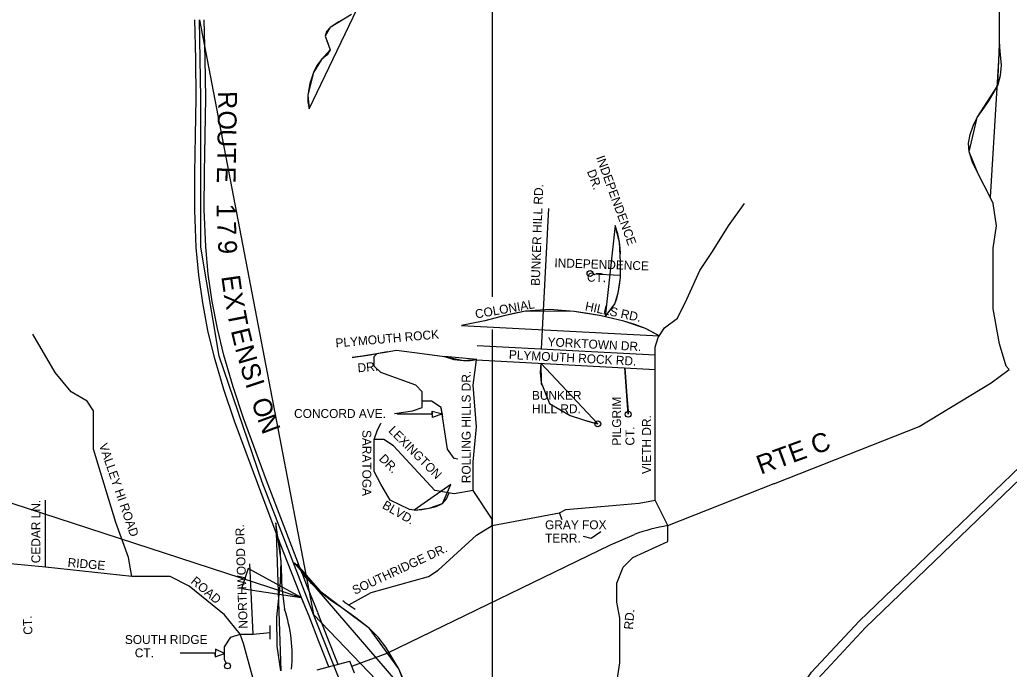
# Model space of a CAD drawing. Extents: x 5.01 to 9.58, y 0.27 to 3.39.
# Drawn here: x 6.828 to 8.037, y 1.17 to 1.964 of the extents above; entities that cross this region are included whole.
import ezdxf

# ---------------------------------------------------------------- set-up
doc = ezdxf.new("R2010")
doc.units = 0
for name, color, linetype in [('Level 7', 7, 'Continuous'), ('MO_001_NOSHOW', 7, 'Continuous'), ('MO_001_VIEW_PV', 7, 'Continuous')]:
    doc.layers.add(name, color=color, linetype=linetype)

msp = doc.modelspace()

# ---------------------------------------------------------------- linework, layer by layer
at = {"layer": 'Level 7'}
msp.add_line((5.7734, 1.7142), (7.1715, 1.2576), dxfattribs=at)
msp.add_lwpolyline([(7.1069, 1.293), (7.0988, 1.2688), (7.1715, 1.2576)], close=True, dxfattribs=at)
at = {"layer": 'MO_001_NOSHOW'}
msp.add_lwpolyline([(7.2329, 1.9703), (7.2071, 1.9544), (7.2009, 1.9437), (7.2071, 1.9269), (7.1965, 1.9153), (7.1867, 1.8993), (7.1796, 1.8718), (7.1814, 1.855), (7.4494, 2.4141)], dxfattribs=at)
for points in [[(7.1867, 1.2369), (7.124, 1.3987), (7.0714, 1.5524), (7.0491, 1.6859), (7.0491, 1.868), (7.0473, 1.9637)], [(8.0132, 1.747), (7.9988, 1.7755), (7.9876, 1.8022), (7.9976, 1.8442), (8.0227, 1.8836), (8.0249, 1.9341)], [(7.543, 1.6007), (7.5549, 1.6167), (7.5588, 1.63), (7.5616, 1.6489), (7.5619, 1.6678), (7.5604, 1.6918), (7.5553, 1.7123)], [(7.609, 1.5773), (7.5923, 1.5864), (7.5659, 1.5954), (7.5379, 1.6017), (7.5053, 1.6072), (7.4455, 1.6076), (7.4175, 1.6013), (7.3959, 1.5958), (7.3676, 1.5902)], [(7.2766, 1.558), (7.2557, 1.5538), (7.2337, 1.5508)], [(7.3468, 1.552), (7.3697, 1.5472), (7.3862, 1.5485)], [(7.4642, 1.544), (7.4646, 1.5203), (7.4748, 1.4947), (7.5004, 1.4802), (7.5179, 1.4743), (7.5339, 1.4699)], [(7.5671, 1.5385), (7.5696, 1.5042), (7.5711, 1.4816)], [(7.3095, 1.3643), (7.3281, 1.3669), (7.3442, 1.3727), (7.3546, 1.3959)], [(7.1468, 1.1678), (7.1423, 1.1983), (7.1417, 1.2336), (7.1465, 1.2762), (7.147, 1.3026), (7.1407, 1.3489)], [(7.3042, 1.1358), (7.2907, 1.1706), (7.255, 1.2198), (7.2211, 1.2449), (7.1942, 1.2653), (7.1631, 1.3001)], [(7.1977, 1.2623), (7.184, 1.2746), (7.1659, 1.2982)], [(7.4942, 0.9161), (7.4334, 0.9173), (7.3323, 0.9598), (7.2615, 1.0589), (7.2211, 1.1499), (7.1867, 1.2369)]]:
    msp.add_lwpolyline(points, close=True, dxfattribs=at)
at = {"layer": 'MO_001_VIEW_PV'}
for p, q in [((7.4051, 2.4135), (7.4051, 1.6251)), ((8.0249, 1.9341), (8.0249, 1.977)), ((7.4651, 1.5616), (7.4741, 1.733)), ((7.6935, 1.7119), (7.7131, 1.7393)), ((8.017, 1.6846), (8.021, 1.7119)), ((8.017, 1.6456), (8.017, 1.6846)), ((7.5281, 1.6534), (7.5617, 1.6517)), ((8.017, 1.6106), (8.017, 1.6456)), ((8.0249, 1.5677), (8.017, 1.6106)), ((7.4051, 1.5854), (7.4051, 0.916)), ((7.3866, 1.5657), (7.6039, 1.5541)), ((7.604, 1.5365), (7.604, 1.5637)), ((7.604, 1.3766), (7.604, 1.5365)), ((7.3316, 1.4819), (7.2889, 1.4819)), ((7.3317, 1.4837), (7.3316, 1.4819)), ((7.3818, 1.3884), (7.3818, 1.4235)), ((7.6195, 1.3455), (7.7495, 1.3969)), ((6.8594, 1.2949), (6.8594, 1.3766)), ((7.6195, 1.3455), (7.604, 1.3766)), ((7.4051, 1.3455), (7.487, 1.3611)), ((7.4904, 1.3526), (7.487, 1.3611)), ((6.8594, 1.2949), (6.8165, 1.2987)), ((6.9646, 1.2831), (6.8594, 1.2949)), ((7.1128, 1.213), (7.1089, 1.2988)), ((6.988, 1.2831), (6.9646, 1.2831)), ((7.0971, 1.213), (7.1128, 1.213)), ((7.1128, 1.213), (7.1335, 1.2149)), ((7.0664, 1.1895), (7.0236, 1.1897)), ((7.0664, 1.1873), (7.0664, 1.1895)), ((7.2334, 1.1737), (7.2765, 1.1896)), ((7.191, 1.1691), (7.231, 1.1798))]:
    msp.add_line(p, q, dxfattribs=at)
for points in [[(7.1745, 1.2513), (7.1461, 1.3238), (7.1185, 1.3966), (7.0901, 1.4732), (7.0771, 1.5118), (7.0657, 1.5509), (7.0577, 1.5841), (7.0513, 1.6177), (7.0465, 1.6515), (7.0433, 1.6855), (7.0415, 1.7311), (7.0417, 1.7767), (7.0433, 1.868), (7.0427, 1.9158), (7.0415, 1.9636)], [(7.1728, 1.2871), (7.1508, 1.3444), (7.1294, 1.4008), (7.1012, 1.4767), (7.0883, 1.5151), (7.077, 1.5539), (7.0692, 1.5866), (7.0629, 1.6196), (7.0581, 1.6529), (7.055, 1.6863), (7.0532, 1.7317), (7.0534, 1.7771), (7.055, 1.8679), (7.0544, 1.9159), (7.0532, 1.9639)], [(7.2278, 1.9669), (7.2174, 1.9613), (7.2071, 1.9544), (7.2027, 1.9494), (7.2009, 1.9437), (7.2043, 1.935), (7.2071, 1.9269), (7.2032, 1.921), (7.1965, 1.9153), (7.1906, 1.9077), (7.1867, 1.8993), (7.182, 1.8859), (7.1796, 1.8718), (7.1799, 1.8633), (7.1814, 1.855)], [(8.0132, 1.747), (8.0059, 1.7611), (7.9988, 1.7755), (7.9921, 1.7886), (7.9876, 1.8022), (7.987, 1.8128), (7.9888, 1.8236), (7.9925, 1.8341), (7.9976, 1.8442), (8.0111, 1.8639), (8.0227, 1.8836), (8.0261, 1.8957), (8.0273, 1.9084), (8.0249, 1.9341)], [(8.021, 1.7119), (8.0171, 1.7392), (8.0132, 1.747)], [(7.5617, 1.6775), (7.5612, 1.6847), (7.5604, 1.6918), (7.5583, 1.7022), (7.5553, 1.7123)], [(7.6039, 1.5638), (7.6078, 1.5755), (7.6156, 1.5872), (7.6312, 1.5989), (7.6429, 1.6223), (7.6585, 1.6573), (7.6741, 1.6807), (7.6936, 1.7119)], [(7.5543, 1.6154), (7.5546, 1.616), (7.5549, 1.6167), (7.5572, 1.6232), (7.5588, 1.63), (7.5605, 1.6394), (7.5616, 1.6489), (7.5617, 1.6503), (7.5617, 1.6517)], [(7.609, 1.5773), (7.6008, 1.5821), (7.5923, 1.5864), (7.5793, 1.5914), (7.5659, 1.5954), (7.552, 1.5988), (7.5379, 1.6017), (7.5217, 1.6047), (7.5053, 1.6072), (7.4753, 1.6095), (7.4455, 1.6076), (7.4314, 1.6048), (7.4175, 1.6013), (7.4067, 1.5985), (7.3959, 1.5958), (7.3818, 1.5928), (7.3676, 1.5902)], [(6.9646, 1.2831), (6.9607, 1.3065), (6.9451, 1.3494), (6.9179, 1.4391), (6.9179, 1.4858), (6.9101, 1.4975), (6.8906, 1.5092), (6.8711, 1.5326), (6.8438, 1.5794)], [(7.2766, 1.558), (7.2882, 1.5599), (7.3193, 1.556), (7.3466, 1.5521), (7.3468, 1.552)], [(8.0366, 1.5365), (8.0327, 1.5404), (8.0249, 1.5677)], [(7.2766, 1.558), (7.2662, 1.5558), (7.2557, 1.5538), (7.2447, 1.5522), (7.2337, 1.5508)], [(7.3193, 1.4975), (7.3193, 1.5092), (7.3116, 1.517), (7.2687, 1.5326), (7.2609, 1.5404), (7.2609, 1.5521), (7.2641, 1.5553)], [(7.3468, 1.552), (7.358, 1.5487), (7.3697, 1.5472), (7.378, 1.5474), (7.3862, 1.5485)], [(7.3817, 1.517), (7.3856, 1.5482), (7.6039, 1.5365)], [(7.4642, 1.544), (7.4635, 1.5322), (7.4646, 1.5203), (7.4649, 1.5188), (7.4652, 1.5173)], [(7.5671, 1.5385), (7.5684, 1.5214), (7.5696, 1.5042), (7.5703, 1.4947), (7.5709, 1.4852)], [(7.7511, 1.3975), (7.9264, 1.4667), (8.0147, 1.5199), (8.0366, 1.5365)], [(7.3817, 1.4235), (7.3856, 1.4663), (7.3817, 1.517)], [(7.2857, 1.4827), (7.3077, 1.4858), (7.3193, 1.4897), (7.3193, 1.4975)], [(7.3445, 1.4786), (7.3427, 1.4897), (7.331, 1.4975), (7.3193, 1.4975)], [(7.3631, 1.4266), (7.3583, 1.4274), (7.3505, 1.4391), (7.3428, 1.4896)], [(7.3316, 1.4819), (7.3317, 1.4855), (7.3441, 1.4822), (7.3319, 1.4777), (7.3317, 1.4837)], [(7.5028, 1.4793), (7.5103, 1.4767), (7.5179, 1.4743), (7.5258, 1.472), (7.5339, 1.4699)], [(7.2609, 1.4508), (7.2648, 1.4624), (7.2687, 1.4702), (7.2693, 1.4708)], [(7.3095, 1.3643), (7.3038, 1.365), (7.2804, 1.3767), (7.2687, 1.3962), (7.2609, 1.4118), (7.2609, 1.4508)], [(7.3817, 1.3884), (7.3583, 1.3845), (7.335, 1.3884), (7.2843, 1.443), (7.2726, 1.4508), (7.2609, 1.4508)], [(7.7288, 0.918), (7.7481, 1.0688), (7.7715, 1.1311), (7.7949, 1.1662), (7.8534, 1.2286), (8.06, 1.4274)], [(7.7399, 0.9151), (7.7404, 0.9167), (7.7598, 1.0648), (7.7832, 1.1233), (7.8027, 1.1584), (7.8612, 1.2208), (8.0717, 1.4235)], [(7.3095, 1.3643), (7.3188, 1.3652), (7.3281, 1.3669), (7.3367, 1.3689), (7.3442, 1.3727), (7.3492, 1.3783), (7.3525, 1.3855)], [(7.4051, 1.3455), (7.4051, 1.3533), (7.3817, 1.3884)], [(7.487, 1.3611), (7.4948, 1.365), (7.5376, 1.3689), (7.5844, 1.3728), (7.6039, 1.3767)], [(7.2297, 1.2485), (7.257, 1.2637), (7.3272, 1.2831), (7.3388, 1.2909), (7.3856, 1.3338), (7.4051, 1.3455)], [(7.5376, 1.057), (7.5376, 1.0843), (7.5532, 1.1272), (7.561, 1.1779), (7.561, 1.2325), (7.5571, 1.252), (7.5571, 1.2753), (7.5649, 1.2948), (7.5766, 1.3065), (7.6195, 1.326), (7.6195, 1.3455)], [(7.2765, 1.1896), (7.5493, 1.3221), (7.5788, 1.3348)], [(7.5376, 1.3377), (7.526, 1.3299), (7.5163, 1.3323)], [(7.0972, 1.213), (7.0777, 1.2364), (7.0348, 1.2714), (7.0114, 1.2831), (6.988, 1.2831)], [(7.1977, 1.2623), (7.1906, 1.2682), (7.184, 1.2746), (7.1779, 1.2813), (7.1722, 1.2886)], [(7.1858, 1.2545), (7.1795, 1.2703), (7.1722, 1.2886)], [(7.1921, 1.2391), (7.1878, 1.2496), (7.1835, 1.2602)], [(7.3042, 1.1358), (7.2983, 1.1535), (7.2907, 1.1706), (7.275, 1.197), (7.2656, 1.209), (7.255, 1.2198), (7.2385, 1.2329), (7.2211, 1.2449), (7.2092, 1.2533), (7.1977, 1.2623)], [(7.1813, 1.2347), (7.177, 1.2452), (7.1727, 1.2557)], [(7.2377, 1.243), (7.2316, 1.2472), (7.2255, 1.2513), (7.2239, 1.2524), (7.2223, 1.2535)], [(7.2053, 1.1729), (7.193, 1.2038), (7.1812, 1.2349)], [(7.2167, 1.1759), (7.2042, 1.2074), (7.1921, 1.2389)], [(7.1338, 1.2065), (7.1335, 1.2149), (7.1335, 1.2233)], [(7.08, 1.1772), (7.0777, 1.1818), (7.0777, 1.1974), (7.0855, 1.2091), (7.0972, 1.213)], [(7.1128, 1.1584), (7.1011, 1.2013), (7.0972, 1.213)], [(7.0664, 1.1895), (7.0665, 1.1851), (7.0779, 1.1891), (7.0669, 1.1943), (7.0664, 1.1873)], [(7.2369, 1.1652), (7.234, 1.1725), (7.231, 1.1797)]]:
    msp.add_lwpolyline(points, dxfattribs=at)
for centre in [(7.5245, 1.6536), (7.5711, 1.4816), (7.5339, 1.4699), (7.0816, 1.174)]:
    msp.add_circle(centre, 0.00362, dxfattribs=at)
for centre, radius, start, end in [((-25.8412, 86.4437), 91.4402, 291.552403, 291.553436), ((7.661, 1.1061), 0.243, 99.8332, 109.767), ((6.0122, 1.222), 1.1376, 3.798, 5.2869), ((7.4383, 1.2926), 0.2911, 179.0664, 189.7474), ((6.9774, 1.1859), 0.1832, 355.0186, 18.2687)]:
    msp.add_arc(centre, radius, start, end, dxfattribs=at)

# ---------------------------------------------------------------- texts
for s, height, rotation, p in [('R', 0.0229, 270.6841, (7.0701, 1.8764)), ('O', 0.0229, 268.993, (7.07, 1.8531)), ('U', 0.0229, 268.993, (7.0696, 1.8303)), ('T', 0.0229, 268.993, (7.0692, 1.8074)), ('INDEPENDENCE', 0.01087, 290, (7.5317, 1.7955)), ('E', 0.0229, 268.993, (7.0688, 1.7846)), ('   DR.', 0.01087, 290, (7.5164, 1.7899)), ('BUNKER HILL RD.', 0.01087, 88, (7.463, 1.6384)), ('1', 0.0229, 269.7847, (7.0685, 1.739)), ('7', 0.0229, 272.218, (7.069, 1.7168)), ('9', 0.0229, 272.218, (7.0699, 1.694)), ('INDEPENDENCE', 0.01087, 358, (7.4808, 1.6614)), ('E', 0.0229, 278.1301, (7.0739, 1.65)), ('          CT.', 0.01087, 358, (7.4802, 1.6452)), ('X', 0.0229, 280.8494, (7.0768, 1.6281)), ('COLONIAL', 0.01087, 10, (7.3851, 1.5985)), ('T', 0.0229, 280.8494, (7.0811, 1.6056)), ('HILLS RD.', 0.01087, 348, (7.5177, 1.6088)), ('E', 0.0229, 283.5119, (7.0855, 1.5839)), ('PLYMOUTH ROCK', 0.01087, 5, (7.214, 1.5632)), ('YORKTOWN DR.', 0.01087, 357, (7.4724, 1.5648)), ('N', 0.0229, 286.2395, (7.0905, 1.5623)), ('PLYMOUTH ROCK RD.', 0.01087, 357, (7.4251, 1.5492)), ('S', 0.0229, 286.2395, (7.0968, 1.5404)), ('      DR.', 0.01087, 5, (7.2168, 1.5307)), ('I', 0.0229, 288.5714, (7.1031, 1.5191)), ('ROLLING HILLS DR.', 0.01087, 90, (7.3786, 1.3974)), ('O', 0.0229, 288.5714, (7.1104, 1.4974)), ('PILGRIM', 0.01087, 90, (7.5624, 1.4433)), ('N', 0.0229, 290.3744, (7.1177, 1.4762)), ('VIETH DR.', 0.01087, 90, (7.5989, 1.4086)), ('LEXINGTON', 0.01087, 315, (7.2775, 1.4608)), ('CT.', 0.01087, 90, (7.5787, 1.4433)), ('SARATOGA', 0.01087, 270, (7.2463, 1.4624)), ('RTE C', 0.02319, 20, (7.733, 1.4077)), ('VALLEY HI ROAD', 0.01087, 289, (6.9243, 1.4439)), ('    DR.', 0.01087, 315, (7.2544, 1.4378)), ('CEDAR LN.', 0.01087, 90, (6.8528, 1.2995)), ('BLVD.', 0.01087, 330, (7.2697, 1.3674)), ('NORTHWOOD DR.', 0.01087, 92, (7.1063, 1.2197)), ('SOUTHRIDGE DR.', 0.01087, 25, (7.2371, 1.2608)), ('RIDGE', 0.01087, 355, (6.8859, 1.2952)), ('ROAD', 0.01087, 320, (7.0359, 1.276)), ('     CT.', 0.01087, 93, (6.8445, 1.1922)), ('RD.', 0.01087, 85, (7.5767, 1.2181))]:
    msp.add_text(s, height=height, rotation=rotation, dxfattribs=at).set_placement(p)
for s, p in [('BUNKER', (7.4535, 1.4993)), ('CONCORD AVE.', (7.1629, 1.4771)), ('HILL RD.', (7.4535, 1.4829)), ('GRAY FOX', (7.4695, 1.3411)), ('TERR.', (7.4695, 1.3248)), ('SOUTH RIDGE', (6.9562, 1.2008)), ('   CT.', (6.9562, 1.1845))]:
    msp.add_text(s, height=0.01087, dxfattribs=at).set_placement(p)

doc.saveas('drawing.dxf')
